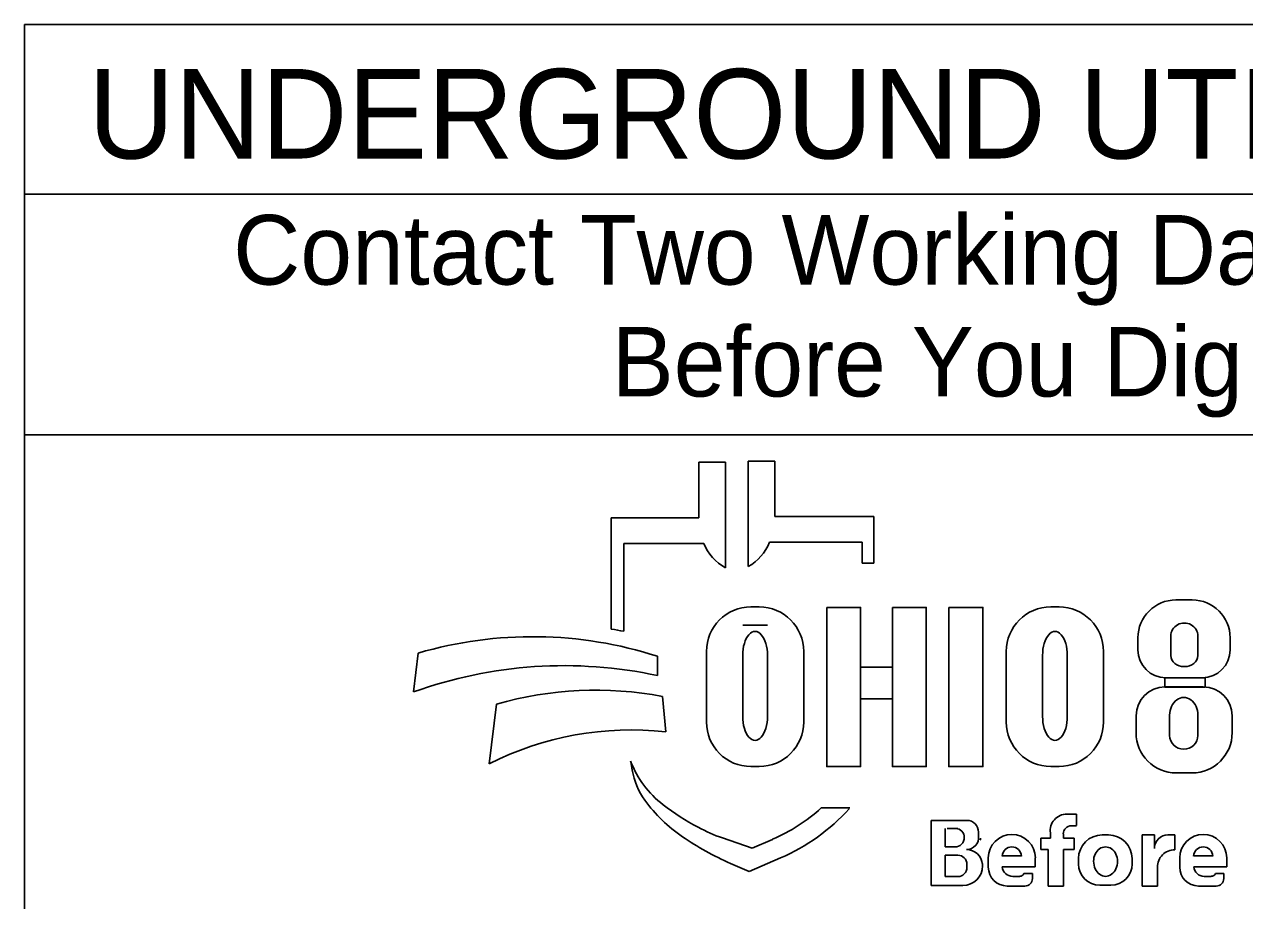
# Model space of a CAD drawing. Extents: x -17 to 88, y -5 to 22.
# Drawn here: x 58.769 to 61.223, y -2.572 to -0.811 of the extents above; entities that cross this region are included whole.
import ezdxf

# ---------------------------------------------------------------- set-up
doc = ezdxf.new("R2010")
doc.units = 0
doc.layers.add('SH_Data', color=7, linetype='Continuous')
doc.layers.add('SH_Text', color=7, linetype='Continuous')

msp = doc.modelspace()

# ---------------------------------------------------------------- linework, layer by layer
at = {"layer": 'SH_Data'}
for p, q in [((58.7689, -3.1481), (58.7689, -0.8106)), ((63.0189, -0.8106), (58.7689, -0.8106)), ((58.7689, -1.1522), (63.0189, -1.1522)), ((58.7689, -1.6356), (63.0189, -1.6356))]:
    msp.add_line(p, q, dxfattribs=at)
at = {"layer": 'SH_Text'}
for p, q in [((60.125, -1.8026), (60.125, -1.6911)), ((60.125, -1.6911), (60.1786, -1.6911)), ((60.1786, -1.6911), (60.1786, -1.9032)), ((60.2243, -1.9009), (60.2243, -1.6888)), ((60.2243, -1.6888), (60.2779, -1.6888)), ((60.2779, -1.6888), (60.2779, -1.8003)), ((59.949, -2.0265), (59.949, -1.8026)), ((59.949, -1.8026), (60.125, -1.8026)), ((60.2779, -1.8003), (60.4772, -1.8003)), ((60.4772, -1.8003), (60.4772, -1.8941)), ((59.9743, -1.8541), (59.9743, -2.0309)), ((60.1354, -1.8541), (59.9743, -1.8541)), ((60.4539, -1.8518), (60.2675, -1.8518)), ((60.4539, -1.8941), (60.4539, -1.8518)), ((60.4772, -1.8941), (60.4539, -1.8941)), ((60.23, -1.9818), (60.2465, -1.9818)), ((60.833, -1.9818), (60.8495, -1.9818)), ((61.0845, -1.9678), (61.1173, -1.9678)), ((60.2632, -2.0188), (60.2134, -2.0188)), ((61.0082, -2.0684), (61.0082, -2.0441)), ((61.0744, -2.0798), (61.0744, -2.0405)), ((61.1285, -2.0405), (61.1285, -2.0798)), ((61.1936, -2.0441), (61.1936, -2.0684)), ((59.5516, -2.1528), (59.561, -2.0747)), ((60.0423, -2.0812), (60.0423, -2.12)), ((60.1405, -2.2133), (60.1405, -2.0713)), ((60.2134, -2.2019), (60.2134, -2.0796)), ((60.2632, -2.0796), (60.2632, -2.2019)), ((60.336, -2.0713), (60.336, -2.2133)), ((60.7435, -2.2133), (60.7435, -2.0713)), ((60.8164, -2.2019), (60.8164, -2.0796)), ((60.8662, -2.0796), (60.8662, -2.2019)), ((60.939, -2.0713), (60.939, -2.2133)), ((61.1376, -2.1244), (61.0642, -2.1244)), ((61.0624, -2.1427), (61.1397, -2.1427)), ((59.7035, -2.2974), (59.7182, -2.1772)), ((60.0523, -2.1618), (60.0585, -2.2328)), ((61.0045, -2.2347), (61.0045, -2.2006)), ((61.072, -2.2406), (61.072, -2.1997)), ((61.1289, -2.1997), (61.1289, -2.2406)), ((61.1976, -2.2006), (61.1976, -2.2347)), ((59.9912, -2.3103), (59.9881, -2.2923)), ((60.2465, -2.3028), (60.23, -2.3028)), ((60.8495, -2.3028), (60.833, -2.3028)), ((61.1167, -2.3156), (61.0855, -2.3156)), ((60.3715, -2.3861), (60.4289, -2.3861)), ((60.8653, -2.3984), (60.8848, -2.3984)), ((60.8848, -2.3984), (60.8848, -2.4214)), ((60.5927, -2.5419), (60.5927, -2.4112)), ((60.5927, -2.4112), (60.6639, -2.4112)), ((60.6207, -2.4646), (60.6207, -2.4277)), ((60.6459, -2.4277), (60.6246, -2.4277)), ((60.8848, -2.4218), (60.8746, -2.4218)), ((60.173, -2.4465), (60.2324, -2.467)), ((60.2324, -2.467), (60.2735, -2.4492)), ((60.6877, -2.4349), (60.6877, -2.4428)), ((60.8127, -2.4697), (60.8127, -2.4468)), ((60.8127, -2.4468), (60.8321, -2.4468)), ((60.8321, -2.4468), (60.8321, -2.4363)), ((60.8582, -2.4383), (60.8582, -2.4468)), ((60.8582, -2.4468), (60.8797, -2.4468)), ((60.8797, -2.4468), (60.8797, -2.4697)), ((60.9365, -2.4402), (60.9487, -2.4402)), ((61.0168, -2.5431), (61.0168, -2.4404)), ((61.0168, -2.4404), (61.0413, -2.4404)), ((61.0413, -2.4404), (61.0413, -2.4673)), ((61.0686, -2.4404), (61.0825, -2.4404)), ((61.0825, -2.4404), (61.0825, -2.4701)), ((60.6401, -2.4646), (60.6207, -2.4646)), ((60.8276, -2.4697), (60.8127, -2.4697)), ((60.8276, -2.5431), (60.8276, -2.4697)), ((60.8797, -2.4697), (60.8582, -2.4697)), ((60.8582, -2.4697), (60.8582, -2.5431)), ((60.2264, -2.514), (60.1891, -2.4976)), ((60.2897, -2.4866), (60.2264, -2.514)), ((60.6207, -2.5241), (60.6207, -2.4812)), ((60.6207, -2.4812), (60.6462, -2.4812)), ((60.6644, -2.4993), (60.6644, -2.5057)), ((60.6957, -2.5022), (60.6957, -2.5026)), ((60.7073, -2.5051), (60.7073, -2.4867)), ((60.7739, -2.4827), (60.7353, -2.4827)), ((60.8018, -2.4867), (60.8018, -2.5044)), ((60.8887, -2.4988), (60.8887, -2.488)), ((60.9965, -2.488), (60.9965, -2.4988)), ((61.0922, -2.5051), (61.0922, -2.4867)), ((61.1588, -2.4827), (61.1203, -2.4827)), ((61.1867, -2.4867), (61.1867, -2.5044)), ((60.646, -2.5241), (60.6207, -2.5241)), ((60.8018, -2.5044), (60.7354, -2.5044)), ((60.7563, -2.5236), (60.7704, -2.5236)), ((60.779, -2.518), (60.7959, -2.518)), ((60.7959, -2.518), (60.7959, -2.5279)), ((61.0473, -2.505), (61.0473, -2.5431)), ((61.1867, -2.5044), (61.1203, -2.5044)), ((61.1412, -2.5236), (61.1554, -2.5236)), ((61.1639, -2.518), (61.1808, -2.518)), ((61.1808, -2.518), (61.1808, -2.5279)), ((60.6564, -2.5419), (60.5927, -2.5419)), ((60.7807, -2.5431), (60.7453, -2.5431)), ((60.8582, -2.5431), (60.8276, -2.5431)), ((60.9537, -2.5416), (60.9315, -2.5416)), ((61.0473, -2.5431), (61.0168, -2.5431)), ((61.1656, -2.5431), (61.1302, -2.5431))]:
    msp.add_line(p, q, dxfattribs=at)
for points in [[(60.3824, -1.9829), (60.4503, -1.9829), (60.4503, -2.3028), (60.3824, -2.3028)], [(60.5145, -1.9829), (60.5825, -1.9829), (60.5825, -2.3028), (60.5145, -2.3028)], [(60.6278, -1.9829), (60.6966, -1.9829), (60.6966, -2.3028), (60.6278, -2.3028)], [(60.4503, -2.1028), (60.5145, -2.1028), (60.5145, -2.1668), (60.4503, -2.1668)], [(61.0621, -2.1244), (61.1437, -2.1244), (61.1437, -2.1429), (61.0621, -2.1429)]]:
    msp.add_lwpolyline(points, close=True, dxfattribs=at)
for centre, radius, start, end in [((60.2267, -1.8173), 0.0985, 201.9296, 240.7469), ((60.1762, -1.815), 0.0985, 299.2531, 338.0704), ((60.23, -2.0713), 0.0895, 90, 180), ((60.2465, -2.0713), 0.0895, 0, 90), ((60.833, -2.0713), 0.0895, 90, 180), ((60.8495, -2.0713), 0.0895, 0, 90), ((61.0845, -2.0441), 0.0763, 90, 180), ((61.1173, -2.0441), 0.0763, 0, 90), ((59.8209, -2.8355), 0.8191, 79.2074, 81.0007), ((59.7911, -2.8608), 0.8191, 72.1402, 106.3144), ((61.0642, -2.0684), 0.056, 180, 270), ((61.1376, -2.0684), 0.056, 270, 0), ((59.8542, -2.9919), 0.8919, 77.8238, 109.8274), ((59.9181, -2.8816), 0.7322, 79.44, 105.8467), ((61.0624, -2.2006), 0.0579, 90, 180), ((61.1397, -2.2006), 0.0579, 0, 90), ((59.9901, -2.8648), 0.6357, 83.8248, 116.8021), ((60.23, -2.2133), 0.0895, 180, 270), ((60.2465, -2.2133), 0.0895, 270, 0), ((60.833, -2.2133), 0.0895, 180, 270), ((60.8495, -2.2133), 0.0895, 270, 0), ((61.0855, -2.2347), 0.081, 180, 270), ((61.1167, -2.2347), 0.081, 270, 0), ((60.1755, -2.2202), 0.2008, 201.0457, 232.5314), ((60.1325, -2.2862), 0.1433, 189.6817, 216.0884), ((60.2661, -2.1887), 0.3088, 216.0884, 235.7167), ((60.368, -1.969), 0.5173, 232.5314, 241.794), ((60.1301, -2.1187), 0.3602, 293.4582, 312.0712), ((60.1301, -2.1187), 0.401, 293.4582, 317.8286), ((60.8653, -2.4319), 0.0335, 90, 187.5187), ((60.2829, -2.1278), 0.3371, 241.794, 250.9821), ((60.642, -2.4446), 0.0169, 357.8325, 90), ((60.6639, -2.4349), 0.0238, 0, 90), ((60.8746, -2.4383), 0.0165, 90, 180), ((60.4326, -1.9445), 0.6044, 235.7167, 246.2325), ((60.6401, -2.4459), 0.0187, 270, 2.0582), ((60.6635, -2.4456), 0.0243, 270, 6.6529), ((60.6741, -2.4471), 0.0175, 347.4023, 0), ((60.7546, -2.4867), 0.0473, 0, 180), ((60.9365, -2.488), 0.0478, 90, 180), ((60.9487, -2.488), 0.0478, 0, 90), ((61.0682, -2.4673), 0.0269, 89.2449, 180), ((61.1395, -2.4867), 0.0473, 0, 180), ((60.6636, -2.502), 0.0321, 4.0748, 90), ((60.7546, -2.4837), 0.0193, 2.9632, 177.0368), ((61.0822, -2.505), 0.0349, 89.6033, 180), ((61.1395, -2.4837), 0.0193, 2.9632, 177.0368), ((60.6462, -2.4993), 0.0181, 0, 90), ((60.6564, -2.5026), 0.0393, 270, 0), ((60.6628, -2.5022), 0.033, 0, 11.7502), ((60.9315, -2.4988), 0.0428, 180, 270), ((60.9537, -2.4988), 0.0428, 270, 0), ((60.646, -2.5057), 0.0184, 270, 0), ((60.7453, -2.5051), 0.038, 180, 270), ((60.7563, -2.5026), 0.021, 184.827, 270), ((60.7704, -2.5142), 0.00938, 270, 335.9979), ((61.1302, -2.5051), 0.038, 180, 270), ((61.1412, -2.5026), 0.021, 184.827, 270), ((61.1554, -2.5142), 0.00938, 270, 335.9979), ((60.7807, -2.5279), 0.0152, 270, 0), ((61.1656, -2.5279), 0.0152, 270, 0)]:
    msp.add_arc(centre, radius, start, end, dxfattribs=at)
for centre, major_axis, ratio, start_param, end_param in [((60.2383, -2.0796), (0, 0.0484), 0.514403, 4.712389, 7.853982), ((60.8413, -2.0796), (0, 0.0484), 0.514403, 4.712389, 7.853982), ((61.1015, -2.0405), (0.0271, 0), 0.969373, 0, 3.141593), ((61.1015, -2.0798), (0.0271, 0), 0.818453, 3.141593, 6.283185), ((61.1004, -2.1997), (0, 0.0358), 0.794529, 4.712389, 7.853982), ((60.2383, -2.2019), (0, 0.0484), 0.514403, 1.570796, 4.712389), ((60.8413, -2.2019), (0, 0.0484), 0.514403, 1.570796, 4.712389), ((61.1004, -2.2406), (0.0284, 0), 0.959837, 3.141593, 6.283185), ((60.9431, -2.4934), (0, 0.029), 0.832186, 4.712389, 7.853982), ((60.9431, -2.4934), (0, 0.0302), 0.797287, 1.570796, 4.712389)]:
    msp.add_ellipse(centre, major_axis=major_axis, ratio=ratio, start_param=start_param, end_param=end_param, dxfattribs=at)

# ---------------------------------------------------------------- texts
for s, height, p in [('UNDERGROUND UTILITIES', 0.18, (58.8971, -1.0803)), ('Contact Two Working Days', 0.14, (59.1886, -1.3338)), ('Before You Dig', 0.14, (59.9498, -1.5588))]:
    msp.add_text(s, height=height, dxfattribs=at).set_placement(p)

doc.saveas('drawing.dxf')
